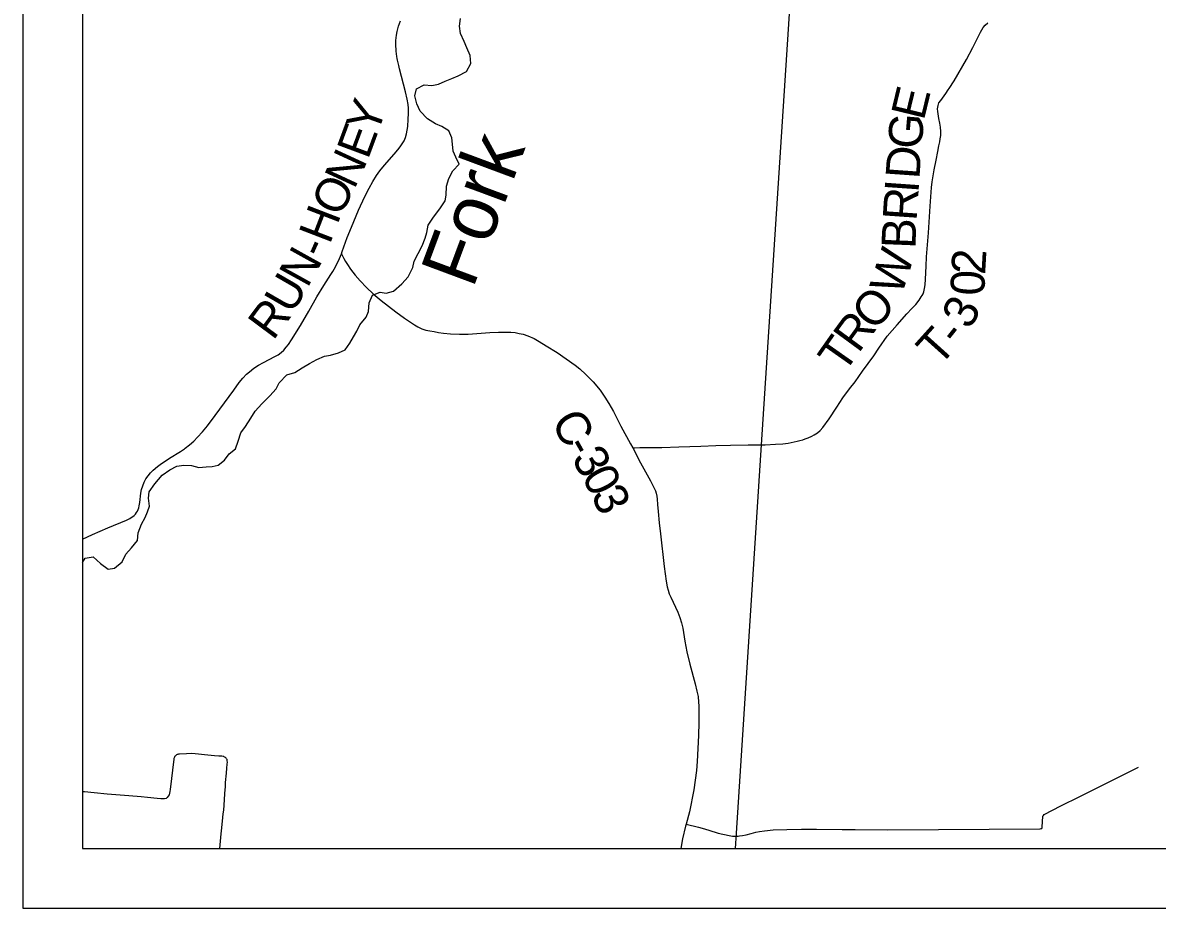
# Model space of a CAD drawing. Extents: x 0 to 34, y 0 to 22.
# Drawn here: x 1.876 to 3.772, y 14.105 to 15.584 of the extents above; entities that cross this region are included whole.
import ezdxf

# ---------------------------------------------------------------- set-up
doc = ezdxf.new("R2010")
doc.units = 0
for name, color, linetype in [('GM_X_County_Road', 7, 'Continuous'), ('GM_X_County_Road_Text', 7, 'Continuous'), ('GM_X_Major_River', 7, 'Continuous'), ('GM_X_Major_River_Text', 7, 'Continuous'), ('GM_X_Township_Road', 7, 'Continuous'), ('GM_X_Township_Road_Text', 7, 'Continuous'), ('GM_X_Township_Text', 7, 'Continuous'), ('SH_Data', 7, 'Continuous')]:
    doc.layers.add(name, color=color, linetype=linetype)

msp = doc.modelspace()

# ---------------------------------------------------------------- linework, layer by layer
at = {"layer": 'GM_X_County_Road'}
for points in [[(1.9763, 14.7214), (1.993, 14.7293), (2.0186, 14.7406), (2.0497, 14.7535), (2.0552, 14.7561), (2.0578, 14.7577), (2.0603, 14.7594), (2.0625, 14.7614), (2.0645, 14.7636), (2.0663, 14.766), (2.0679, 14.7686), (2.0692, 14.7713), (2.0702, 14.7742), (2.071, 14.7771), (2.0721, 14.7831), (2.0739, 14.7986), (2.075, 14.8048), (2.0768, 14.8108), (2.0792, 14.8166), (2.0822, 14.8222), (2.0858, 14.8274), (2.0898, 14.8322), (2.0943, 14.8367), (2.1013, 14.8428), (2.1062, 14.8464), (2.1218, 14.8567), (2.1401, 14.8683), (2.1464, 14.8726), (2.1478, 14.8736), (2.155, 14.8793), (2.162, 14.8854), (2.1686, 14.8919), (2.1769, 14.901), (2.1848, 14.9106), (2.1977, 14.928), (2.2289, 14.9705), (2.2381, 14.983), (2.244, 14.9903), (2.2505, 14.9971), (2.2551, 15.0013), (2.2625, 15.0071), (2.2703, 15.0123), (2.2784, 15.0168), (2.2978, 15.0265), (2.3031, 15.0296), (2.308, 15.0333), (2.3125, 15.0374), (2.3166, 15.042), (2.3203, 15.0468), (2.3255, 15.0545), (2.3403, 15.0782), (2.3543, 15.1023), (2.368, 15.1265), (2.3794, 15.1451), (2.3912, 15.1633), (2.3946, 15.1684), (2.3991, 15.1764), (2.4056, 15.1904), (2.4087, 15.198), (2.4102, 15.2018), (2.4186, 15.2252), (2.4256, 15.2425), (2.4376, 15.2711), (2.4479, 15.2938), (2.4549, 15.3077), (2.4612, 15.3188), (2.4674, 15.3286), (2.4732, 15.3368), (2.4806, 15.3459), (2.4972, 15.3646), (2.5033, 15.3716), (2.5071, 15.3765), (2.5105, 15.3816), (2.5135, 15.3869), (2.5158, 15.3925), (2.5175, 15.3984), (2.5188, 15.4044), (2.5196, 15.4105), (2.5206, 15.4228), (2.5209, 15.4321), (2.5207, 15.4413), (2.5201, 15.4474), (2.5187, 15.4563), (2.516, 15.4683), (2.506, 15.5069), (2.5048, 15.5126), (2.5025, 15.5212), (2.5019, 15.5243), (2.5012, 15.5273), (2.5002, 15.5366), (2.4997, 15.5483), (2.4999, 15.5541), (2.5008, 15.5629), (2.5019, 15.569), (2.5044, 15.5781), (2.5075, 15.5869)], [(2.4087, 15.198), (2.4127, 15.1905), (2.4155, 15.1853), (2.4188, 15.18), (2.4241, 15.1723), (2.4318, 15.1624), (2.4401, 15.153), (2.4509, 15.1417), (2.4618, 15.131), (2.4752, 15.12), (2.5, 15.101), (2.5142, 15.0904), (2.5227, 15.0848), (2.531, 15.0793), (2.5367, 15.0764), (2.5434, 15.073), (2.5499, 15.0708), (2.5568, 15.0693), (2.5639, 15.0681), (2.5708, 15.0669), (2.5794, 15.0658), (2.5911, 15.0647), (2.6062, 15.064), (2.6208, 15.064), (2.6422, 15.0657), (2.6567, 15.0666), (2.6711, 15.0672), (2.6835, 15.0672), (2.6921, 15.067), (2.699, 15.0665), (2.7057, 15.0652), (2.7125, 15.0637), (2.7202, 15.0613), (2.7309, 15.0567), (2.7393, 15.0519), (2.7511, 15.0445), (2.7692, 15.0334), (2.7996, 15.0119), (2.8069, 15.0058), (2.8173, 14.9967), (2.8295, 14.9844), (2.8409, 14.9706), (2.8491, 14.959), (2.8558, 14.9484), (2.8632, 14.9347), (2.8756, 14.9101), (2.8919, 14.8808), (2.8955, 14.8741), (2.9087, 14.849), (2.9254, 14.819), (2.931, 14.8081), (2.9334, 14.8024), (2.9349, 14.7984), (2.936, 14.7934), (2.9363, 14.7883), (2.937, 14.7793), (2.938, 14.7681), (2.9398, 14.7491), (2.942, 14.7307), (2.9483, 14.6761), (2.9514, 14.6515), (2.953, 14.6423), (2.9545, 14.6363), (2.9565, 14.6304), (2.9589, 14.6247), (2.9672, 14.608), (2.971, 14.5996), (2.9742, 14.5909), (2.9769, 14.5821), (2.979, 14.573), (2.9828, 14.5516), (2.9861, 14.5337), (2.991, 14.5128), (2.9997, 14.4799), (3.0028, 14.4679), (3.0046, 14.4589), (3.0056, 14.4497), (3.0058, 14.4436), (3.0059, 14.432), (3.0059, 14.4157), (3.0054, 14.3939), (3.0034, 14.3505), (3.0021, 14.3355), (2.9976, 14.3032), (2.9901, 14.2666), (2.9847, 14.2457), (2.9839, 14.2426), (2.9789, 14.2215), (2.9757, 14.2054)]]:
    msp.add_lwpolyline(points, dxfattribs=at)
at = {"layer": 'GM_X_Major_River'}
for points in [[(2.4398, 15.0795), (2.4504, 15.0925), (2.4541, 15.102), (2.4552, 15.1164), (2.4608, 15.1289), (2.4737, 15.1339), (2.4835, 15.1324), (2.496, 15.1359), (2.5096, 15.1477), (2.5205, 15.1595), (2.5284, 15.1751), (2.5306, 15.1857), (2.537, 15.1986), (2.5438, 15.2111), (2.5487, 15.224), (2.5517, 15.2335), (2.5535, 15.2461), (2.5629, 15.2594), (2.5735, 15.2734), (2.5821, 15.2864), (2.5836, 15.2958), (2.5843, 15.311), (2.5884, 15.3239), (2.5948, 15.3368), (2.6054, 15.3475), (2.5997, 15.3592), (2.5955, 15.3694), (2.5943, 15.3812), (2.5935, 15.3914), (2.5885, 15.4031), (2.5764, 15.4106), (2.5658, 15.4151), (2.5525, 15.4234), (2.5404, 15.4362), (2.535, 15.4483), (2.5316, 15.4616), (2.5342, 15.4737), (2.547, 15.4799), (2.5599, 15.4788), (2.5712, 15.4811), (2.5822, 15.4865), (2.5935, 15.4907), (2.6037, 15.4953), (2.6177, 15.5025), (2.6249, 15.5158), (2.624, 15.5291), (2.6183, 15.542), (2.6137, 15.5525), (2.6076, 15.5658), (2.6061, 15.5783), (2.6079, 15.5908)], [(1.9763, 14.6829), (1.9806, 14.6898), (1.9938, 14.6921), (2.0063, 14.6812), (2.0189, 14.6714), (2.0298, 14.6733), (2.0427, 14.6836), (2.0487, 14.6965), (2.0581, 14.7072), (2.0679, 14.7193), (2.069, 14.7322), (2.075, 14.7467), (2.081, 14.7581), (2.0848, 14.7675), (2.0881, 14.777), (2.0866, 14.7903), (2.0877, 14.8009), (2.0971, 14.8142), (2.1095, 14.8283), (2.1224, 14.8375), (2.1337, 14.8436), (2.1454, 14.8451), (2.1583, 14.8444), (2.1704, 14.8415), (2.1829, 14.8427), (2.1927, 14.8431), (2.2029, 14.845), (2.2135, 14.8538), (2.221, 14.864), (2.232, 14.8724), (2.2361, 14.8853), (2.2406, 14.8994), (2.2485, 14.91), (2.2572, 14.9237), (2.2647, 14.9355), (2.276, 14.9477), (2.2892, 14.961), (2.2998, 14.9728), (2.305, 14.9827), (2.3175, 14.996), (2.3307, 14.9998), (2.3435, 15.0075), (2.3556, 15.0147), (2.3677, 15.0216), (2.3806, 15.0274), (2.3904, 15.0289), (2.404, 15.0328), (2.4153, 15.0377), (2.4229, 15.0491), (2.4289, 15.0594), (2.4345, 15.0689), (2.4398, 15.0795)]]:
    msp.add_lwpolyline(points, dxfattribs=at)
at = {"layer": 'GM_X_Township_Road'}
for points in [[(3.1144, 14.8794), (3.1168, 14.8794), (3.1343, 14.8802), (3.1461, 14.8808), (3.1552, 14.8821), (3.1704, 14.8852), (3.1745, 14.8862), (3.1795, 14.8875), (3.1837, 14.8889), (3.1887, 14.8908), (3.1947, 14.8936), (3.1989, 14.8958), (3.2042, 14.8994), (3.2088, 14.9033), (3.2132, 14.908), (3.2235, 14.9223), (3.2366, 14.9423), (3.2468, 14.9576), (3.2578, 14.9724), (3.2672, 14.9844), (3.2794, 15.002), (3.2981, 15.0278), (3.3068, 15.0403), (3.3207, 15.0605), (3.3371, 15.0797), (3.3533, 15.0979), (3.3621, 15.1067), (3.3684, 15.1136), (3.3742, 15.1208), (3.3776, 15.126), (3.3792, 15.1287), (3.3805, 15.1315), (3.3816, 15.1344), (3.3824, 15.1374), (3.3831, 15.1404), (3.384, 15.1465), (3.3846, 15.1558), (3.3855, 15.1775), (3.3863, 15.193), (3.3898, 15.233), (3.3924, 15.2777), (3.3947, 15.3087), (3.3957, 15.318), (3.3994, 15.338), (3.4025, 15.3543), (3.4051, 15.3687), (3.407, 15.3783), (3.4084, 15.3849), (3.4094, 15.3898), (3.4099, 15.3926), (3.4102, 15.3957), (3.4102, 15.4024), (3.4096, 15.4094), (3.4086, 15.416), (3.4068, 15.4241), (3.4051, 15.4356), (3.4048, 15.4401), (3.4056, 15.4456), (3.4071, 15.4499), (3.41, 15.4542), (3.4184, 15.4657), (3.4227, 15.4718), (3.4244, 15.4743), (3.4323, 15.487), (3.453, 15.5223), (3.464, 15.5424), (3.4707, 15.5556), (3.4765, 15.5681), (3.4809, 15.5757), (3.4841, 15.5796), (3.4888, 15.5839)], [(2.8955, 14.8741), (2.8986, 14.8742), (2.9074, 14.8745), (2.9196, 14.8745), (2.9444, 14.8749), (2.9723, 14.8756), (3.0094, 14.8772), (3.0342, 14.8781), (3.059, 14.8786), (3.0886, 14.8789), (3.1132, 14.8793), (3.1144, 14.8794)], [(2.2056, 14.2054), (2.2068, 14.2177), (2.2081, 14.2299), (2.209, 14.2397), (2.2106, 14.2572), (2.2114, 14.2634), (2.2123, 14.2693), (2.2137, 14.2867), (2.2143, 14.297), (2.215, 14.3088), (2.2154, 14.3152), (2.2167, 14.3311), (2.2175, 14.3394), (2.2181, 14.3461), (2.2183, 14.3492), (2.2181, 14.3517), (2.2177, 14.3536), (2.217, 14.3547), (2.216, 14.3562), (2.215, 14.357), (2.2137, 14.3579), (2.2124, 14.3586), (2.2111, 14.3591), (2.2092, 14.3595), (2.2072, 14.3596), (2.2041, 14.3596), (2.1969, 14.36), (2.1801, 14.3618), (2.1698, 14.3628), (2.1588, 14.3636), (2.1499, 14.3635), (2.1385, 14.3629), (2.1375, 14.3629), (2.1365, 14.3627), (2.1353, 14.3624), (2.1342, 14.362), (2.1331, 14.3614), (2.1319, 14.3605), (2.1309, 14.3595), (2.1302, 14.3586), (2.1297, 14.3577), (2.1292, 14.3566), (2.1289, 14.3553), (2.1287, 14.3542), (2.1229, 14.3035), (2.1223, 14.3004), (2.1217, 14.2974), (2.1208, 14.2948), (2.1194, 14.2925), (2.1177, 14.2904), (2.1158, 14.289), (2.1134, 14.2883), (2.1106, 14.2881), (2.1073, 14.2882), (2.1008, 14.2888), (2.0851, 14.2904), (2.074, 14.2914), (2.0534, 14.2932), (2.0176, 14.2962), (1.9958, 14.2982), (1.9794, 14.2998), (1.9763, 14.3)], [(3.3209, 14.2363), (3.576, 14.2381), (3.5781, 14.2384), (3.5787, 14.2385), (3.5791, 14.2388), (3.5794, 14.2395), (3.5797, 14.2411), (3.5808, 14.2593), (3.5816, 14.2606), (3.5831, 14.2619), (3.6107, 14.2766), (3.6426, 14.2923), (3.6827, 14.3119), (3.7406, 14.3412)], [(2.9847, 14.2457), (3.0056, 14.2406), (3.0153, 14.2381), (3.0351, 14.232), (3.0381, 14.231), (3.0564, 14.2267), (3.0622, 14.2257), (3.0677, 14.2256), (3.0698, 14.2258), (3.0719, 14.2261)], [(3.0719, 14.2261), (3.0741, 14.2263), (3.0791, 14.2271), (3.0852, 14.2282), (3.0934, 14.2303), (3.101, 14.2324), (3.1072, 14.2338), (3.1158, 14.235), (3.1303, 14.2362), (3.1528, 14.237), (3.1776, 14.2375), (3.2004, 14.2377)], [(3.2004, 14.2377), (3.2023, 14.2377), (3.2455, 14.2368), (3.267, 14.2369), (3.3209, 14.2363)]]:
    msp.add_lwpolyline(points, dxfattribs=at)
at = {"layer": 'GM_X_Township_Text'}
msp.add_lwpolyline([(8.7763, 18.7365), (7.7116, 18.8006), (7.6851, 18.802), (7.2653, 18.8305), (6.9608, 18.8511), (6.9477, 18.852), (6.9018, 18.8551), (6.7713, 18.864), (6.3469, 18.8928), (5.4766, 18.9518), (4.3125, 19.0308), (4.2973, 19.0318), (4.1694, 19.0405), (3.3833, 19.0938), (3.2714, 17.3671), (3.2279, 16.6952), (3.1822, 15.9898), (3.1607, 15.6594), (3.1102, 14.8789), (3.0682, 14.2309), (3.0665, 14.2054)], dxfattribs=at)
at = {"layer": 'SH_Data'}
for p, q in [((1.8763, 21.1054), (1.8763, 14.1054)), ((1.9763, 21.0054), (1.9763, 14.2054)), ((1.9763, 14.2054), (8.7763, 14.2054)), ((1.9763, 14.2054), (1.9763, 14.2054)), ((1.8763, 14.1054), (8.8763, 14.1054))]:
    msp.add_line(p, q, dxfattribs=at)

# ---------------------------------------------------------------- texts
at = {"layer": 'GM_X_County_Road_Text'}
for s, rotation, p in [('Y', 70.3131, (2.4681, 15.3948)), ('E', 69.6477, (2.4531, 15.3542)), ('N', 65.2103, (2.4303, 15.3044)), ('O', 63.0684, (2.4066, 15.2577)), ('H', 68.9626, (2.3893, 15.2125)), ('N', 61.0033, (2.3519, 15.1396)), ('-', 65.9203, (2.3785, 15.1881)), ('U', 60.0583, (2.3265, 15.0954)), ('R', 53.3557, (2.2946, 15.0519)), ('C', 299.7294, (2.7578, 14.9176)), ('-', 299.6074, (2.7809, 14.8771)), ('3', 299.1911, (2.7924, 14.8569)), ('0', 297.5588, (2.8093, 14.8267)), ('3', 294.4655, (2.8251, 14.7964))]:
    msp.add_text(s, height=0.0568, rotation=rotation, dxfattribs=at).set_placement(p)
at = {"layer": 'GM_X_Major_River_Text'}
msp.add_text('Fork', height=0.0947, rotation=69.6047, dxfattribs=at).set_placement((2.6283, 15.1381))
at = {"layer": 'GM_X_Township_Road_Text'}
for s, rotation, p in [('E', 76.3899, (3.3817, 15.4192)), ('G', 85.237, (3.3779, 15.3716)), ('D', 86.0064, (3.3744, 15.3219)), ('R', 86.0078, (3.3696, 15.2521)), ('I', 86, (3.3728, 15.2987)), ('B', 87.7142, (3.3677, 15.2059)), ('W', 71.9262, (3.3443, 15.1266)), ('2', 86.772, (3.4842, 15.1623)), ('0', 87.6706, (3.4828, 15.1275)), ('O', 49.1197, (3.2995, 15.0674)), ('3', 61.743, (3.4589, 15.0699)), ('R', 53.7999, (3.2727, 15.0307)), ('T', 48.0106, (3.4074, 15.008)), ('-', 51.2855, (3.4381, 15.0423)), ('T', 54.9406, (3.2484, 14.9962))]:
    msp.add_text(s, height=0.0568, rotation=rotation, dxfattribs=at).set_placement(p)

doc.saveas('drawing.dxf')
